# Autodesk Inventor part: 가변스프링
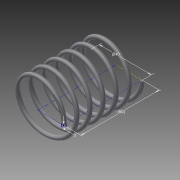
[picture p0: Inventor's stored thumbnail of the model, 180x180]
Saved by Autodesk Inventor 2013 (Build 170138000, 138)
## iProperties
Created: 2018-02
Part Number: 가변스프링
Material: 일반
Document SubType Name: Modeling
Designer: Administrator
Density: 1 g/cm^3
Author: Administrator
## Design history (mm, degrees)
sketch "스케치1"
  geometry: L1 (0, 0)-(20, 0); L2 (20, 0)-(20, 47.25); L3 (20, 47.25)-(0, 47.25); L4 (0, 47.25)-(0, 0); C1 r 1.5 at (20, 0)
  constraints: 8 end point, 2 parallel, 1 centre point, 1 coincident, 1 horizontal, 1 perpendicular
  dimensions: "d0" = 40 diameter of L2 L4; "d2" = 47.25 distance of L1.end L2.end (derived); "d3" = 3 diameter of C1
feature "코일1" pitch "d4" = 10; turns "d6" = 6; dims "d5" = 47.25 (= d2), "d7" = 0, angle "d8" = 90 deg, angle "d9" = 90 deg, "d10" = 0, "d11" = 0
sketch "스케치2"
  geometry: L1 (-18.5, 0)-(-21.5, 0) reference; 1 further point
  constraints: 1 horizontal alignment
extrude "돌출1" cut sketch "스케치2" stored distance "d12" = 10; taper "d13" = 0 deg
node "작업 평면1"
sketch "스케치3"
  geometry: L1 (-1.5, 0)-(1.5, 0) reference; 1 further point
  constraints: 1 horizontal alignment
extrude "돌출2" cut sketch "스케치3" stored distance "d14" = 10; taper "d15" = 0 deg
node "솔리드1"
node "절단 모서리 투영1"
node "절단 모서리 투영2"
